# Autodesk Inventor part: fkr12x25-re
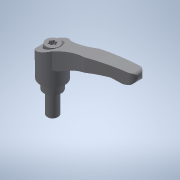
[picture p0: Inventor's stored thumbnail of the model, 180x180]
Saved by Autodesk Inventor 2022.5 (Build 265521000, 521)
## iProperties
Created: 2017-09
Part Number: fkr12x25-re
Material: 一般
Document SubType Name: Modeling
Designer: imaocorp
Density: 1 g/cm^3
Appearance: 既定
Author: imaocorp
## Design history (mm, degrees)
node "fkr12x25-re.x_t1"
node "fkr12x25-re"
node "Base1"
